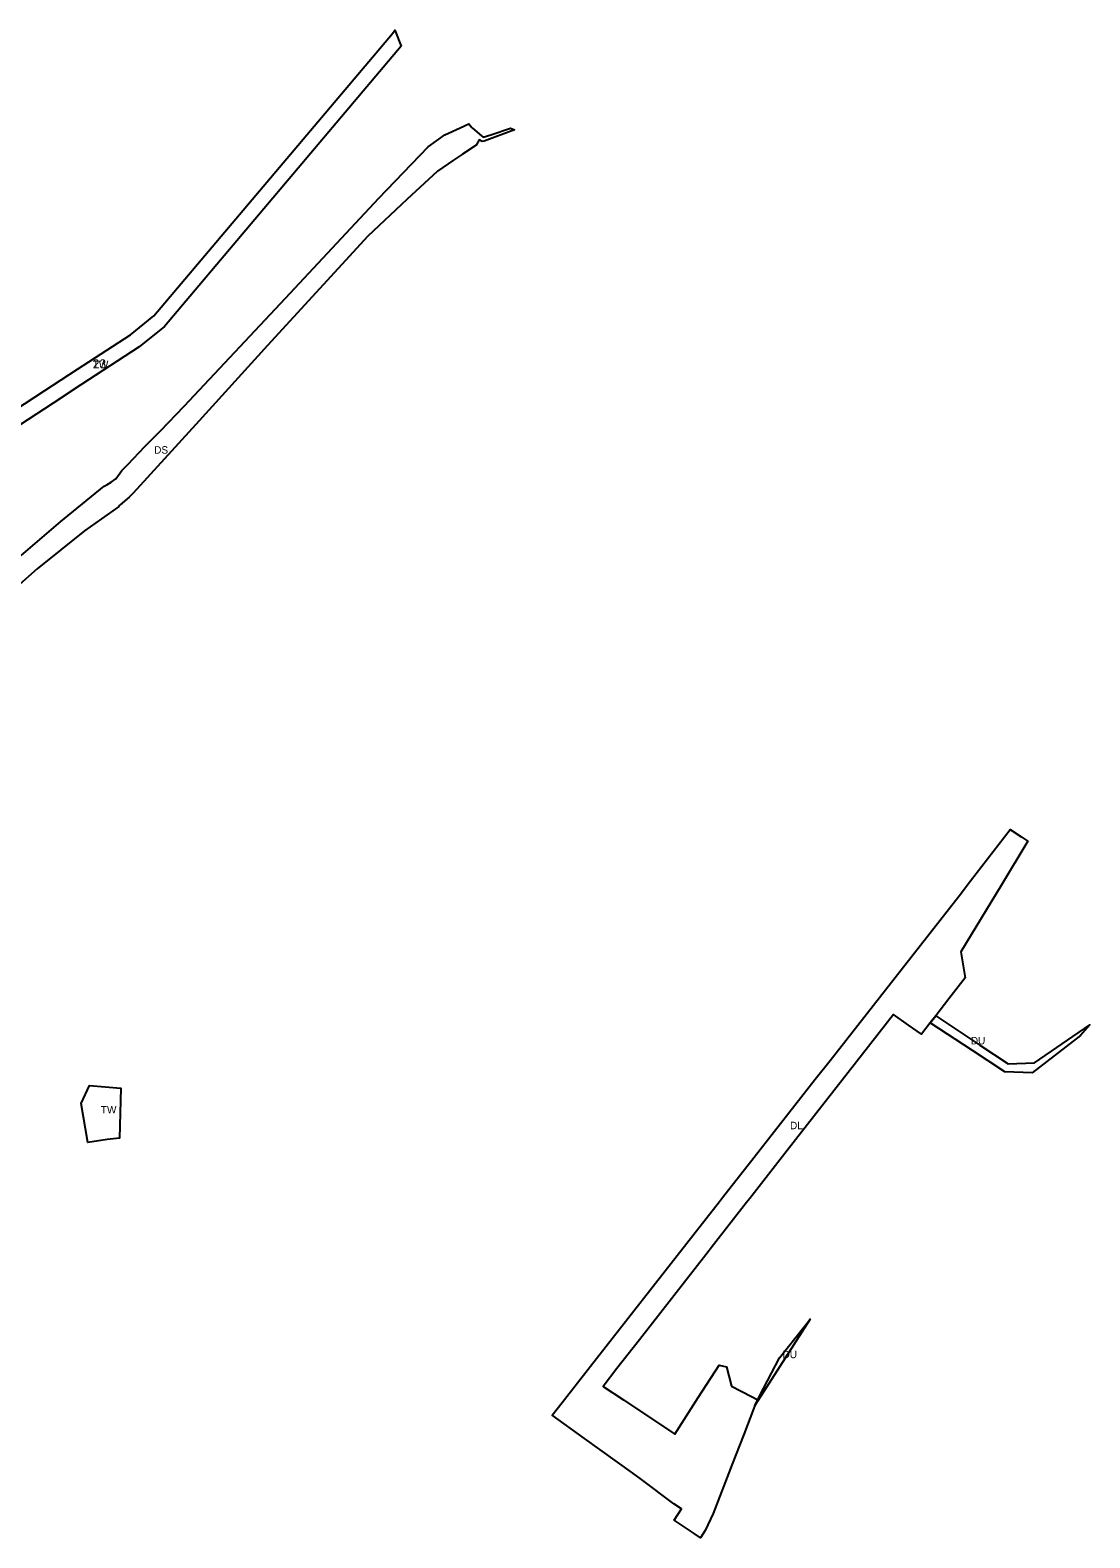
# Model space of a CAD drawing. Extents: x -519992 to -518210, y -1182334 to -1179965.
# Drawn here: x -519254 to -518546, y -1180987 to -1179980 of the extents above; entities that cross this region are included whole.
import ezdxf

# ---------------------------------------------------------------- set-up
doc = ezdxf.new("R2010")
doc.units = 0
for name, color, linetype in [('90310013', 7, 'Continuous'), ('90320013', 7, 'Continuous'), ('90340013', 7, 'Continuous'), ('90390013', 7, 'Continuous'), ('90390023', 7, 'Continuous'), ('ID_navrh', 7, 'Continuous')]:
    doc.layers.add(name, color=color, linetype=linetype)

msp = doc.modelspace()

# ---------------------------------------------------------------- linework, layer by layer
at = {"layer": '90310013'}
for points in [[(-518584.99, -1180676.84), (-518603.24, -1180676.18), (-518624.83, -1180661.96), (-518652.93, -1180643.43), (-518649.3, -1180638.71), (-518619.78, -1180658.29), (-518600.95, -1180670.78), (-518583.43, -1180670.18), (-518546.41, -1180644.74), (-518552.75, -1180651.93)], [(-518737.39, -1180846.67), (-518733.13, -1180841.32), (-518770.01, -1180898.85), (-518768.05, -1180895.07), (-518766.86, -1180892.78), (-518753.55, -1180867.09)]]:
    msp.add_lwpolyline(points, close=True, dxfattribs=at)
at = {"layer": '90320013'}
msp.add_lwpolyline([(-519259.97, -1180331.39), (-519233.45, -1180308.61), (-519231.03, -1180306.54), (-519204.49, -1180285.08), (-519202.667, -1180284.047), (-519199.69, -1180282.36), (-519196.77, -1180280.19), (-519192.584, -1180274.543), (-519192.5, -1180274.43), (-519188.71, -1180270.5), (-519177.22, -1180258.6), (-519166.92, -1180247.95), (-519151.14, -1180231.61), (-519083.4, -1180159.52), (-519021.15, -1180092.68), (-518988.12, -1180058.41), (-518977.04, -1180050.38), (-518964.28, -1180044.51), (-518962.96, -1180043.91), (-518960.91, -1180042.97), (-518959.01, -1180045.58), (-518958.48, -1180046.02), (-518952.45, -1180051.06), (-518951.37, -1180051.98), (-518946.3, -1180050.48), (-518933.18, -1180045.84), (-518930.62, -1180047.06), (-518950.88, -1180054.57), (-518952.1, -1180054.93), (-518954.15, -1180053.76), (-518956.07, -1180057.3), (-518965.2, -1180063.4), (-518971.19, -1180067.41), (-518981.94, -1180074.6), (-519002.39, -1180093.57), (-519028.54, -1180118.15), (-519095.46, -1180191.17), (-519143.34, -1180243.85), (-519185.02, -1180289.7), (-519187.77, -1180292.28), (-519193.89, -1180297.38), (-519194.54, -1180297.83), (-519194.84, -1180298.72), (-519217.64, -1180314.85), (-519249.16, -1180340.26), (-519282.81, -1180369.73)], dxfattribs=at)
at = {"layer": '90340013'}
msp.add_lwpolyline([(-518803.2, -1180982.47), (-518806.398, -1180987.297), (-518810.67, -1180984.43), (-518823.9, -1180975.55), (-518819.03, -1180968), (-518824.07, -1180964.69), (-518845.75, -1180948.41), (-518851.55, -1180944.12), (-518883.79, -1180920.87), (-518905.31, -1180905.29), (-518898.78, -1180896.9), (-518879.81, -1180872.74), (-518811.46, -1180785.47), (-518793.68, -1180762.77), (-518791.61, -1180760.13), (-518770.41, -1180733.05), (-518729.72, -1180681.1), (-518719.82, -1180668.45), (-518672.36, -1180607.93), (-518633.73, -1180558.55), (-518626.09, -1180548.61), (-518599.7, -1180514.3), (-518591.76, -1180519.42), (-518587.79, -1180521.97), (-518605.66, -1180551.61), (-518632.43, -1180595.93), (-518629.68, -1180613.23), (-518640.58, -1180627.39), (-518649.3, -1180638.71), (-518652.93, -1180643.43), (-518658.73, -1180650.97), (-518667.48, -1180644.84), (-518677.5, -1180637.82), (-518698.12, -1180664.22), (-518748.4, -1180728.62), (-518773.42, -1180760.66), (-518775.57, -1180763.41), (-518797.69, -1180791.72), (-518802.83, -1180798.37), (-518847.08, -1180854.98), (-518862.16, -1180874.22), (-518871.4, -1180886.12), (-518857.86, -1180895.06), (-518823.56, -1180917.96), (-518807.86, -1180893.62), (-518793.95, -1180872.06), (-518789.09, -1180873.05), (-518785.65, -1180886.11), (-518772.34, -1180892.89), (-518768.05, -1180895.07), (-518770.01, -1180898.85), (-518770.69, -1180900.6), (-518777.5, -1180918.25), (-518785.21, -1180938.18), (-518797.94, -1180971.15)], close=True, dxfattribs=at)
at = {"layer": '90390013'}
msp.add_lwpolyline([(-519202.56, -1180721.35), (-519215.32, -1180723.28), (-519219.9, -1180697.33), (-519214.15, -1180685.3), (-519193.43, -1180686.91), (-519194.14, -1180720.3)], close=True, dxfattribs=at)
at = {"layer": '90390023'}
msp.add_lwpolyline([(-519530.579, -1180429.847), (-519543.828, -1180432.113), (-519507.413, -1180374.043), (-519446.618, -1180338.797), (-519370.805, -1180299.397), (-519337.818, -1180282.254), (-519337.72, -1180282.23), (-519337.489, -1180282.083), (-519327.14, -1180275.48), (-519244.032, -1180221.205), (-519222.249, -1180206.979), (-519186.97, -1180183.94), (-519171.27, -1180171.17), (-519011.96, -1179982.64), (-519010.33, -1179980.49), (-519006.122, -1179991.224), (-519164.235, -1180178.338), (-519181.068, -1180192.03), (-519220.038, -1180217.438), (-519238.561, -1180229.516), (-519332.465, -1180290.741), (-519441.802, -1180347.563), (-519499.747, -1180381.157), (-519503.729, -1180387.445)], close=True, dxfattribs=at)

# ---------------------------------------------------------------- texts
at = {"layer": '90310013'}
for rotation, p in [(360, (-518625.8664, -1180657.775)), (0, (-518751.57, -1180867.3365))]:
    msp.add_text('DU', height=5, rotation=rotation, dxfattribs=at).set_placement(p)
at = {"layer": '90320013'}
msp.add_text('DS', height=5, rotation=0, dxfattribs=at).set_placement((-519171.09, -1180263.319))
at = {"layer": '90340013'}
msp.add_text('DL', height=5, rotation=0, dxfattribs=at).set_placement((-518746.55, -1180714.4189))
at = {"layer": '90390013'}
msp.add_text('TW', height=5, rotation=360, dxfattribs=at).set_placement((-519206.665, -1180703.9263))
at = {"layer": '90390023'}
msp.add_text('TW', height=5, rotation=0, dxfattribs=at).set_placement((-519212.0844, -1180206.3015))
at = {"layer": 'ID_navrh'}
msp.add_text('23', height=6, rotation=0, dxfattribs=at).set_placement((-519212.0844, -1180206.3015))

doc.saveas('drawing.dxf')
